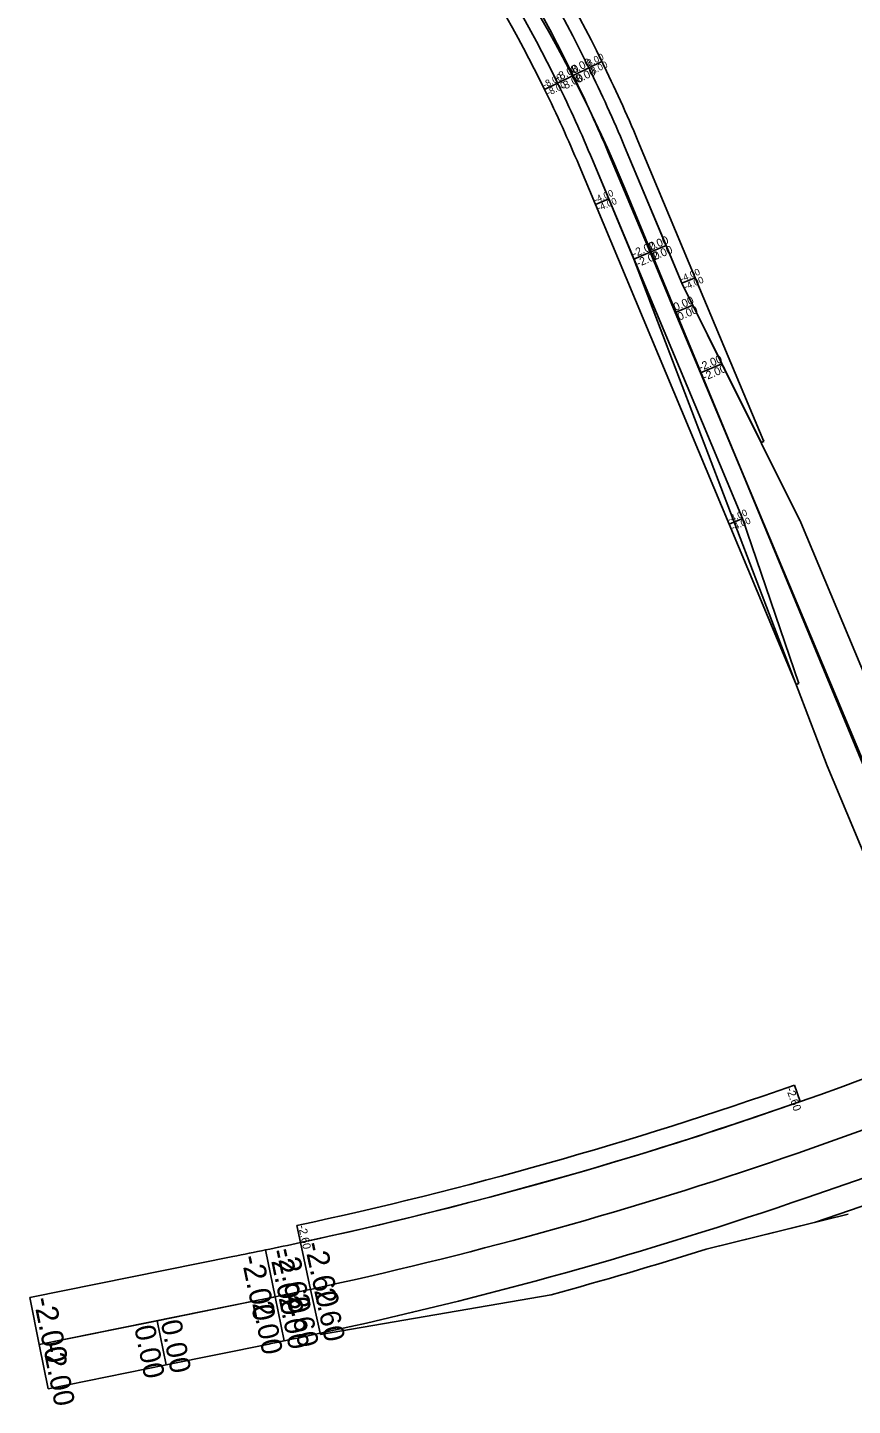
# Model space of a CAD drawing. Extents: x 2342222 to 2351711, y 366548 to 372860.
# Drawn here: x 2347945 to 2348514, y 367459 to 368410 of the extents above; entities that cross this region are included whole.
import ezdxf

# ---------------------------------------------------------------- set-up
doc = ezdxf.new("R2010")
doc.units = 0
for name, color, linetype in [('Default', 7, 'Continuous'), ('RD_PD_Final_LnLine', 7, 'Continuous'), ('RD_PD_SuperShp_REL_LINE-3', 7, 'Continuous'), ('RD_PD_SuperShp_S-97', 7, 'Continuous')]:
    doc.layers.add(name, color=color, linetype=linetype)

msp = doc.modelspace()

# ---------------------------------------------------------------- linework, layer by layer
at = {"layer": 'Default'}
msp.add_line((2348511.05, 367591.31), (2348413.95, 367567.4), dxfattribs=at)
at = {"layer": 'RD_PD_Final_LnLine'}
msp.add_line((2348611.02, 367683.86), (2348357, 368298.46), dxfattribs=at)
msp.add_line((2348611.02, 367683.86), (2348357, 368298.46), dxfattribs=at)
msp.add_arc((2347432.83, 367916.49), 1000, 22.45591, 59.17851, dxfattribs=at)
msp.add_arc((2347432.83, 367916.49), 1000, 22.45591, 59.17851, dxfattribs=at)
at = {"layer": 'RD_PD_SuperShp_REL_LINE-3'}
for p, q in [((2348341.18, 368386.21), (2348332.2, 368381.81)), ((2348341.18, 368386.21), (2348332.2, 368381.81)), ((2348321.42, 368376.53), (2348310.64, 368371.26)), ((2348321.42, 368376.53), (2348310.64, 368371.26)), ((2348321.42, 368376.53), (2348332.2, 368381.81)), ((2348321.42, 368376.53), (2348332.2, 368381.81)), ((2348310.64, 368371.26), (2348301.66, 368366.86)), ((2348301.66, 368366.86), (2348310.64, 368371.26)), ((2348356.81, 368327.55), (2348385.43, 368259.18)), ((2348356.81, 368327.55), (2348396.32, 368233.15)), ((2348405.54, 368237.01), (2348366.03, 368331.42)), ((2348334.67, 368318.29), (2348363.29, 368249.91)), ((2348334.67, 368318.29), (2348345.91, 368291.42)), ((2348374.36, 368254.54), (2348345.74, 368322.92)), ((2348374.36, 368254.54), (2348345.74, 368322.92)), ((2348336.69, 368287.56), (2348325.44, 368314.43)), ((2348345.91, 368291.42), (2348336.69, 368287.56)), ((2348336.69, 368287.56), (2348345.91, 368291.42)), ((2348345.91, 368291.42), (2348438.15, 368071.03)), ((2348428.93, 368067.17), (2348336.69, 368287.56)), ((2348363.29, 368249.91), (2348374.36, 368254.54)), ((2348363.29, 368249.91), (2348374.36, 368254.54)), ((2348385.43, 368259.18), (2348374.36, 368254.54)), ((2348385.43, 368259.18), (2348374.36, 368254.54)), ((2348374.36, 368254.54), (2348391.73, 368213.03)), ((2348374.36, 368254.54), (2348599.83, 367715.82)), ((2348396.32, 368233.15), (2348405.54, 368237.01)), ((2348405.54, 368237.01), (2348396.32, 368233.15)), ((2348396.32, 368233.15), (2348450.96, 368123.3)), ((2348452.81, 368124.07), (2348405.54, 368237.01)), ((2348391.73, 368213.03), (2348403.81, 368218.09)), ((2348391.73, 368213.03), (2348403.81, 368218.09)), ((2348409.1, 368171.52), (2348391.73, 368213.03)), ((2348423.89, 368177.71), (2348409.1, 368171.52)), ((2348409.1, 368171.52), (2348423.89, 368177.71)), ((2348599.83, 367715.82), (2348409.1, 368171.52)), ((2348450.96, 368123.3), (2348452.81, 368124.07)), ((2348438.15, 368071.03), (2348428.93, 368067.17)), ((2348438.15, 368071.03), (2348428.93, 368067.17)), ((2348477.08, 367957.3), (2348438.15, 368071.03)), ((2348428.93, 368067.17), (2348475.24, 367956.53)), ((2348475.24, 367956.53), (2348477.08, 367957.3))]:
    msp.add_line(p, q, dxfattribs=at)
for points in [[(2348403.81, 368218.09), (2348396.32, 368233.15), (2348385.43, 368259.18)], [(2348588.76, 367711.19), (2348565.56, 367766.61), (2348533.06, 367813.18), (2348496.58, 367900.35), (2348363.29, 368249.91)], [(2348403.81, 368218.09), (2348403.81, 368218.09), (2348423.89, 368177.71)], [(2348423.89, 368177.71), (2348478.33, 368068.28), (2348621.96, 367725.09)]]:
    msp.add_lwpolyline(points, dxfattribs=at)
for radius, start, end in [(1022, 26.08411, 55.82062), (1012, 26.08411, 55.82062), (1012, 26.08411, 55.82062), (1000, 26.08411, 55.82062), (1000, 26.08411, 55.82062), (978, 26.08411, 55.82062), (988, 26.08411, 55.82062), (988, 26.08411, 55.82062), (1022, 22.71075, 26.08411), (1000, 22.71075, 26.08411), (1000, 22.71075, 26.08411), (1012, 22.71075, 26.08411), (1012, 22.71075, 26.08411), (978, 22.71075, 26.08411), (988, 22.71075, 26.08411), (988, 22.71075, 26.08411)]:
    msp.add_arc((2347423.27, 367936.84), radius, start, end, dxfattribs=at)
at = {"layer": 'RD_PD_SuperShp_S-97'}
for p, q in [((2348477.94, 367668.9), (2348473.96, 367680.23)), ((2348482.63, 367602.77), (2348620.61, 367650.32)), ((2348620.61, 367650.32), (2348482.63, 367602.77)), ((2348488.49, 367585.75), (2348626.47, 367633.3)), ((2348130.88, 367583.43), (2348133.41, 367571.7)), ((2348413.02, 367567.17), (2348488.49, 367585.75)), ((2348140.36, 367539.44), (2348133.41, 367571.7)), ((2348133.41, 367571.7), (2348140.36, 367539.44)), ((2348086.78, 367562.07), (2347946.65, 367533.71)), ((2348109.23, 367566.6), (2348115.9, 367534.28)), ((2348115.9, 367534.28), (2348109.23, 367566.6)), ((2348146.88, 367509.13), (2348140.36, 367539.44)), ((2348140.36, 367539.44), (2348146.88, 367509.13)), ((2347946.65, 367533.71), (2347953.2, 367501.34)), ((2347953.2, 367501.34), (2348105.35, 367532.13)), ((2348105.35, 367532.13), (2348034.55, 367517.8)), ((2348122.16, 367503.92), (2348115.9, 367534.28)), ((2348115.9, 367534.28), (2348122.16, 367503.92)), ((2348147.07, 367508.25), (2348306.11, 367535.7)), ((2348034.55, 367517.8), (2347953.2, 367501.34)), ((2348040.7, 367487.42), (2348034.55, 367517.8)), ((2348034.55, 367517.8), (2348040.7, 367487.42)), ((2347953.2, 367501.34), (2347959.35, 367470.95)), ((2348040.7, 367487.42), (2348111.5, 367501.74)), ((2348146.88, 367509.13), (2348147.07, 367508.25)), ((2347959.35, 367470.95), (2348040.7, 367487.42))]:
    msp.add_line(p, q, dxfattribs=at)
for radius, start, end in [(2880.79, 282.15209, 295.2191), (2880.79, 282.15209, 295.2191), (2847.79, 282.15209, 291.74619), (2835.79, 282.15209, 289.35922), (2847.79, 282.15209, 289.35923), (2911.79, 282.15209, 289.01476), (2911.79, 282.15209, 289.01476), (2847.79, 281.65487, 282.15209), (2847.79, 281.19404, 281.65487), (2923.79, 285.31354, 287.49765), (2880.79, 281.65487, 282.15209), (2880.79, 281.65487, 282.15209), (2880.79, 281.44073, 281.65487), (2880.79, 281.44073, 281.57602), (2880.79, 281.57602, 281.65487), (2911.79, 281.44073, 281.65487), (2911.79, 281.65487, 282.15209)]:
    msp.add_arc((2347533.93, 370355.68), radius, start, end, dxfattribs=at)

# ---------------------------------------------------------------- texts
at = {"layer": 'RD_PD_SuperShp_REL_LINE-3'}
for s, height, rotation, p in [('8.00', 5.52, 26.08411, (2348321.48, 368377.5)), ('8.00', 4.6, 26.08411, (2348332.25, 368382.61)), ('8.00', 4.6, 26.08411, (2348334.89, 368377.22)), ('-8.00', 4.6, 26.08411, (2348301.71, 368367.66)), ('-8.00', 5.52, 26.08411, (2348310.7, 368372.22)), ('-8.00', 5.52, 26.08411, (2348313.87, 368365.75)), ('8.00', 5.52, 26.08411, (2348324.65, 368371.03)), ('-8.00', 4.6, 26.08411, (2348304.35, 368362.27)), ('-4.00', 4.6, 22.71075, (2348336.79, 368288.36)), ('-4.00', 4.6, 22.71075, (2348339.1, 368282.83)), ('-2.00', 5.52, 22.71075, (2348363.4, 368250.87)), ('2.00', 5.52, 22.71075, (2348374.47, 368255.5)), ('-2.00', 5.52, 22.71075, (2348366.18, 368244.23)), ('2.00', 5.52, 22.71075, (2348377.25, 368248.86)), ('-4.00', 4.6, 22.71075, (2348396.42, 368233.95)), ('-4.00', 4.6, 22.71019, (2348398.91, 368228.49)), ('0.00', 5.52, 22.71075, (2348391.85, 368213.99)), ('0.00', 5.52, 22.71075, (2348394.63, 368207.35)), ('-2.00', 5.52, 22.71075, (2348409.22, 368172.48)), ('-2.00', 5.52, 22.71075, (2348412, 368165.84)), ('-4.00', 0.922, 22.70515, (2348450.95, 368123.44)), ('-4.00', 4.6, 22.71075, (2348429.03, 368067.97)), ('-4.00', 4.6, 22.71075, (2348431.34, 368062.43)), ('-4.00', 0.922, 22.71075, (2348475.26, 367956.69))]:
    msp.add_text(s, height=height, rotation=rotation, dxfattribs=at).set_placement(p)
at = {"layer": 'RD_PD_SuperShp_S-97'}
for s, height, rotation, p in [('-2.60', 5.52, 289.36368, (2348468.12, 367677.67)), ('-2.60', 5.52, 282.15209, (2348131.81, 367583.14)), ('-2.60', 15.18, 282.15209, (2348135.95, 367570.9)), ('-2.00', 15.18, 281.65487, (2348092.37, 367561.78)), ('-2.00', 15.18, 281.65487, (2348111.76, 367565.78)), ('-2.60', 15.18, 282.15209, (2348116.59, 367566.73)), ('2.60', 14.26, 282.15209, (2348142.74, 367538.68)), ('-2.00', 15.192, 281.44073, (2347949.17, 367532.87)), ('2.00', 14.26, 281.65487, (2348100.05, 367529.75)), ('2.00', 14.26, 281.65487, (2348118.27, 367533.51)), ('2.60', 14.26, 282.15209, (2348124.56, 367534.77)), ('0.00', 14.26, 281.44073, (2348018.69, 367513.33)), ('0.00', 14.26, 281.44073, (2348036.92, 367517.01)), ('-2.00', 14.26, 281.44073, (2347955.57, 367500.55)), ('-2.00', 0.418, 282.15209, (2348146.96, 367509.1))]:
    msp.add_text(s, height=height, rotation=rotation, dxfattribs=at).set_placement(p)

doc.saveas('drawing.dxf')
